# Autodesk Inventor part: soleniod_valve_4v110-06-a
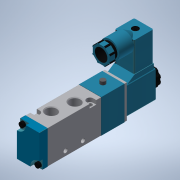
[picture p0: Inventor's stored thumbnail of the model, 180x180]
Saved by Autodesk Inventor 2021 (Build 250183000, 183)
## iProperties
Created: 2018-08
Part Number: soleniod_valve_4v110-06-a
Checked By: TraceParts S.A.
Material: Genérico
Catalog Web Link: www.traceparts.com
Document SubType Name: Modeling
Designer: TraceParts
Density: 1 g/cm^3
Appearance: Turquesa
Company: TraceParts S.A.
REFERENCE: 4V110-06-A
DESIGN: Soleniod Valve(5/2 way,5/3 way) 4V Series 4V110-06-A
SUPPLIER: ZheJiang XingChen pneumatic Co., LTD
TraceParts.PartNumber: 50-16072015-070146
TraceParts.PartTitle: Solenoid Valve(5/2 way,5/3 way) 4V Series
TraceParts.InstanceId: 50-16072015-0701465GDI1SPU4NASLYKM6WDY0ZWWY
TraceParts.PartStatus: Published
TraceParts.PartVersion: 1.2.0
TRACEPARTS: TRACEPARTS
TraceParts.PartLanguage: en
TraceParts.ClassPath: XINGCHEN_PNEUMATIC:/F_XINGCHEN_PNEUMATIC/XINGCHEN_PNEUMATIC.020/XINGCHEN_PNEUMATIC.020.010/50-16072015-070146
Author: TraceParts
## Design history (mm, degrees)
node "Geometría reparada1"
body "Solid1"
node "soleniod_valve_4v110-06-a"
